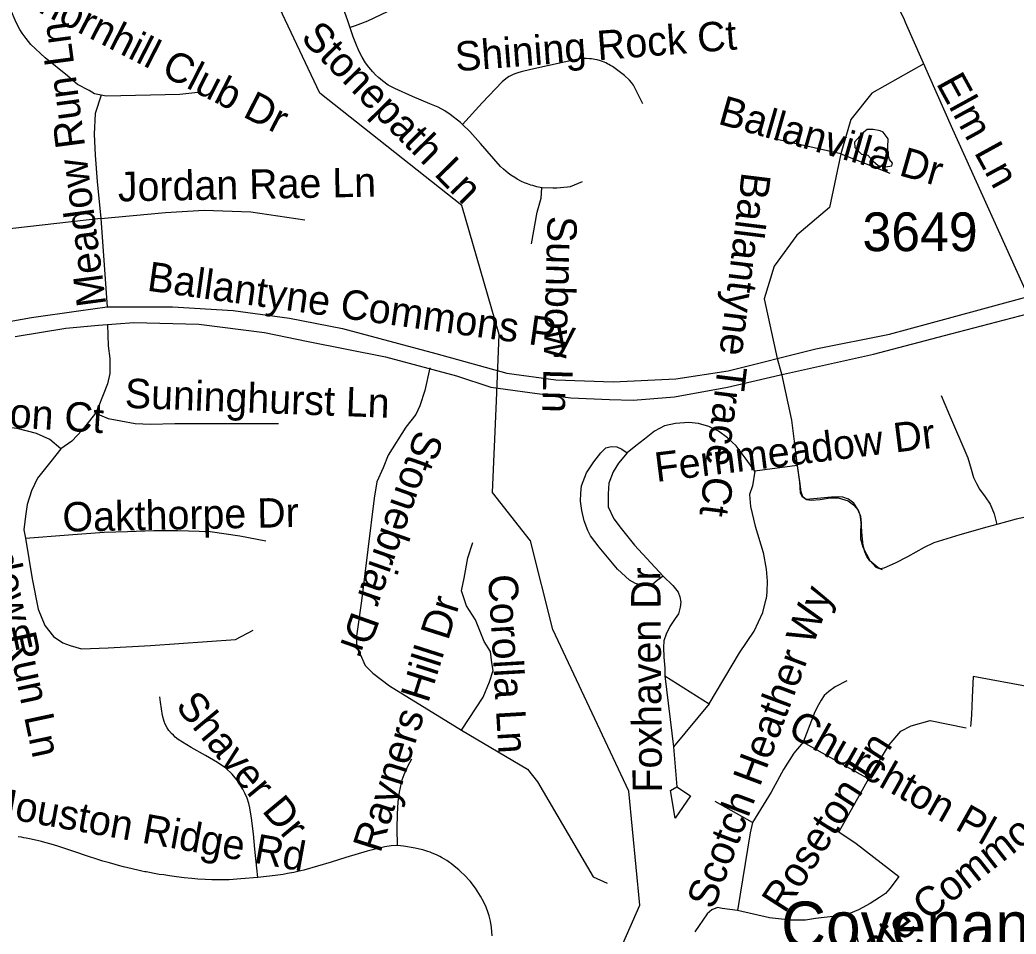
# Model space of a CAD drawing. Extents: x 1383679 to 1536984, y 460658 to 651027.
# Drawn here: x 1453218 to 1456433, y 478691 to 481642 of the extents above; entities that cross this region are included whole.
import ezdxf

# ---------------------------------------------------------------- set-up
doc = ezdxf.new("R2010")
doc.units = 0
for name, color, linetype in [('Exist Cultural Church Label', 7, 'Continuous'), ('Exist Hydrographic Creek Single Shore', 7, 'Continuous'), ('Exist Hydrographic Misc Water Feature', 7, 'Continuous'), ('Exist Road Non-System Type 51', 7, 'Continuous'), ('Exist Road Non-System Type 51 Label', 7, 'Continuous'), ('Exist Road Secondary Type 51 Attributed', 7, 'Continuous'), ('Exist Road Secondary Type 51 Label', 7, 'Continuous'), ('Exist Road Secondary Type 51 Number Label', 7, 'Continuous')]:
    doc.layers.add(name, color=color, linetype=linetype)

msp = doc.modelspace()

# ---------------------------------------------------------------- linework, layer by layer
at = {"layer": 'Exist Hydrographic Creek Single Shore'}
msp.add_lwpolyline([(1454515.4, 478187.7), (1454889, 478340.4), (1455120.5, 478561.6), (1455218.3, 478784.1), (1455183.2, 479152.5), (1454937.8, 479674), (1454865.3, 479959.8), (1454743.1, 480116.4), (1454756.2, 480411.6), (1454764.5, 480626.1), (1454643.5, 481042.1), (1454185.7, 481405.5), (1453861.2, 482093.8), (1453724.2, 482339.5), (1453677.2, 482498), (1453550.2, 482618.2), (1453423.9, 482707.8), (1453281.8, 482670.9), (1452824, 482655.1), (1452497.8, 482823.6), (1452051.2, 482927.9), (1451604.2, 483110.8), (1451358.9, 483344.6)], dxfattribs=at)
at = {"layer": 'Exist Hydrographic Misc Water Feature'}
msp.add_lwpolyline([(1455935.6, 481274.7), (1455911, 481247.3), (1455912.8, 481229.2), (1455934.4, 481208.2), (1455954.4, 481204.6), (1455972, 481186.1), (1455987.8, 481171.9), (1456011.7, 481167.3), (1456031.8, 481171), (1456033.8, 481179.2), (1456024.1, 481190.9), (1456018.5, 481209), (1456018.9, 481231.2), (1456019.4, 481257.4), (1456003.7, 481279.1), (1455993.8, 481283.4), (1455971.8, 481287.9), (1455951.8, 481288.3), (1455935.6, 481274.7)], dxfattribs=at)
at = {"layer": 'Exist Road Non-System Type 51'}
msp.add_line((1453479.1, 481000.2), (1453499, 480715.7), dxfattribs=at)
for points in [[(1454646.3, 481304.4), (1454640.2, 481310.4), (1454606.4, 481336), (1454589.6, 481347.6), (1454567.8, 481359.8), (1454540.8, 481371.1), (1454484.8, 481394.3), (1454427.6, 481420.5), (1454406.5, 481431.2), (1454388.4, 481444.4), (1454375.3, 481455.4), (1454365.5, 481464.8), (1454357.1, 481473.8), (1454343.6, 481488.8), (1454333.6, 481503), (1454322.5, 481521), (1454313.5, 481537.6), (1454309, 481547.2), (1454303.6, 481560.3), (1454293.5, 481586.7), (1454276, 481638.1), (1454241.4, 481735.6), (1454218.8, 481806.1), (1454213.2, 481831.4)], [(1454833.9, 481812.2), (1454739, 481781.7), (1454681, 481765.8), (1454639.6, 481755.8), (1454589.4, 481743.4), (1454572.4, 481739.2), (1454552.5, 481733.3), (1454532.3, 481726.8), (1454515.3, 481719.6), (1454477, 481702.4), (1454423.7, 481677.1), (1454382.4, 481657.4), (1454339.7, 481638), (1454317.4, 481628.9), (1454299.6, 481622.4), (1454283.6, 481617.2)], [(1453480.4, 481398.5), (1453458.7, 481403.1), (1453441.2, 481413.3), (1453403.8, 481432.6), (1453371.1, 481460.9), (1453298.8, 481518.8), (1453253.3, 481562.1), (1453237.9, 481581.2), (1453225.4, 481598.7), (1453217.8, 481610.5), (1453212.3, 481620.5), (1453202, 481640.9), (1453179.1, 481696.8), (1453179, 481698.7)], [(1455228.6, 481370.2), (1455200.4, 481426.3), (1455198.1, 481431.2), (1455191.9, 481439.8), (1455185, 481447.1), (1455169.2, 481461.8), (1455130.2, 481491.2), (1455124.3, 481494.6), (1455118.2, 481498.1), (1455114, 481500.2), (1455109, 481502.8), (1455103.8, 481505.3), (1455098.5, 481507.6), (1455091.2, 481509.9), (1455081.3, 481512.2), (1455073.5, 481513.7), (1455062.4, 481515.5), (1455055.9, 481516.4), (1455045.2, 481517.2), (1455042, 481517.2), (1455038.2, 481517), (1455031.7, 481516.6), (1455023.9, 481515.8), (1454989.1, 481508.6), (1454920.7, 481493.5), (1454866.4, 481481.3), (1454835.1, 481474.2), (1454824.9, 481471.1), (1454815.2, 481467.7), (1454807.2, 481464.3), (1454800.7, 481461.2), (1454797.1, 481459.3), (1454791.4, 481455.9), (1454774, 481441.7), (1454709.3, 481373.8), (1454646.3, 481304.4)], [(1456134.6, 481499.4), (1455967.5, 481404.8), (1455899, 481320.5), (1455867.4, 481209.8)], [(1453792.2, 481407.1), (1453733.6, 481401.3), (1453496.1, 481395.2), (1453480.4, 481398.5)], [(1453480.4, 481398.5), (1453461.1, 481339.7), (1453457.1, 481273.1), (1453461.1, 481205.4), (1453467.1, 481120.2), (1453479.1, 481000.2)], [(1454902.5, 481099.7), (1454891, 481101.5), (1454886.2, 481102.6), (1454873.2, 481106.6), (1454866.4, 481108.3), (1454855.5, 481112.3), (1454846.5, 481115.6), (1454836.4, 481120.2), (1454822.3, 481127.8), (1454815, 481132.4), (1454802.6, 481140.8), (1454793.8, 481147.1), (1454786.1, 481153.2), (1454778.2, 481160.3), (1454769.3, 481168.7), (1454704.8, 481242.2), (1454669.7, 481281.1), (1454646.3, 481304.4)], [(1455867.4, 481209.8), (1455651.5, 481257.3)], [(1455867.4, 481209.8), (1455830.6, 481035.9), (1455725.3, 480946.3), (1455651.5, 480846.2), (1455619.9, 480740.8), (1455661.7, 480548.6)], [(1455867.4, 481209.8), (1456025.4, 481146.6)], [(1455032.4, 481118.7), (1454993.7, 481103), (1454984.7, 481102), (1454950.9, 481099), (1454938, 481098.4), (1454903.5, 481099.6), (1454902.5, 481099.7)], [(1454868.9, 480919.3), (1454887.6, 481021.3), (1454899.7, 481066), (1454902.5, 481099.7)], [(1453479.1, 481000.2), (1453687.6, 481020.1), (1453812.6, 481028), (1453963.2, 481022.4), (1454137.3, 480996.3)], [(1453479.1, 481000.2), (1453195.4, 480968), (1453081.5, 480952.1), (1452990.4, 480927.2), (1452773.2, 480872.8)], [(1453499, 480715.7), (1453710.5, 480715.7), (1453906, 480704.1), (1454087.5, 480678.9), (1454259, 480646), (1454560.2, 480564.8), (1454789.6, 480500.9), (1454947.2, 480479.6), (1455132.7, 480473.8), (1455334.2, 480483.5), (1455503.7, 480508.6), (1455787, 480580.2), (1456024.3, 480627.2), (1456214.6, 480678.6), (1456472, 480748.3)], [(1453092.1, 480651.8), (1453255.7, 480680.9), (1453407.3, 480702.2), (1453499, 480715.7)], [(1453202.5, 480619.8), (1453365.5, 480646.1), (1453471.5, 480656.7), (1453585.6, 480664.6), (1453794.8, 480659.3), (1454006.8, 480632.9), (1454148.1, 480603.9), (1454398.1, 480553.8), (1454626.3, 480493.2), (1454737.7, 480456.3), (1454887.2, 480435.2), (1454995.9, 480422), (1455120.9, 480416.8), (1455196.9, 480414.1), (1455330.1, 480424.7), (1455501.3, 480456.3), (1455672.5, 480495.9), (1455972.2, 480562.9), (1456222.2, 480628.6), (1456494.2, 480699.2)], [(1453500.1, 480657.9), (1453502.8, 480589.8), (1453508.2, 480549), (1453508.2, 480516.3), (1453508.2, 480499.9), (1453500.1, 480467.2), (1453486.5, 480431.8), (1453470.1, 480390.9), (1453462, 480371.8)], [(1455661.7, 480548.6), (1455675.5, 480499.1)], [(1454540.8, 480518.9), (1454524.5, 480445.3), (1454508.2, 480396.3), (1454495.9, 480367.6), (1454463.2, 480326.7), (1454406, 480236.8), (1454389.7, 480195.9), (1454369.2, 480150.9), (1454361.1, 480097.8), (1454320.2, 479766.6), (1454303.9, 479652.1), (1454303.9, 479627.6), (1454316.1, 479594.9), (1454332.5, 479558.1), (1454357, 479533.5), (1454410.1, 479492.6), (1454643, 479349.5)], [(1455675.5, 480499.1), (1455707.6, 480349.3), (1455726.1, 480203.8)], [(1456190.6, 480429.7), (1456214.5, 480372.9), (1456277, 480227.8), (1456287.6, 480191.7), (1456295, 480164.6), (1456304.5, 480145.2), (1456314.8, 480126.8), (1456332.9, 480102.1), (1456349.2, 480078.7), (1456361.6, 480047), (1456371.1, 480013.1)], [(1453462, 480371.8), (1453418.4, 480317.4), (1453385.7, 480281.9), (1453350.3, 480257.4)], [(1453462, 480371.8), (1453502.8, 480355.5), (1453543.6, 480347.3), (1453589.9, 480339.2), (1453638.9, 480336.4), (1453717.9, 480339.2), (1454052.8, 480339.2)], [(1455589.9, 480185.3), (1455557.9, 480228.1), (1455529.4, 480267.3), (1455500.9, 480292.3), (1455472.3, 480313.7), (1455441, 480329.2), (1455408.2, 480338.6), (1455376.1, 480342.2), (1455333.4, 480338.6), (1455297.7, 480331.5), (1455265.6, 480313.7), (1455233.6, 480288.7), (1455205.1, 480267.3), (1455178.1, 480244.4)], [(1453350.3, 480257.4), (1453314.9, 480287.4), (1453271.4, 480306.5), (1453208.7, 480322.8), (1453159.7, 480328.3), (1453110.7, 480331), (1453059, 480325.5), (1453018.1, 480314.6), (1452974.6, 480298.3), (1452917.4, 480265.6)], [(1453350.3, 480257.4), (1453317.6, 480216.5), (1453274.1, 480162), (1453255, 480121.2), (1453241.4, 480077.6), (1453236, 480039.4), (1453230.5, 479995.8), (1453236, 479968.6)], [(1455294.2, 479846.5), (1455274, 479831.7), (1455260.3, 479820.5), (1455245.4, 479815.5), (1455222.9, 479816.7), (1455204.2, 479823), (1455185.6, 479833), (1455146.9, 479869.1), (1455087.1, 479940.2), (1455059.7, 479976.3), (1455051, 479993.8), (1455038.5, 480025), (1455031.1, 480058.6), (1455027.3, 480088.6), (1455028.6, 480113.5), (1455029.8, 480137.2), (1455046, 480179.6), (1455069.7, 480215.7), (1455092.1, 480244.4), (1455108.3, 480260.6), (1455125.7, 480264.4), (1455144.4, 480263.1), (1455160.6, 480255.6), (1455178.1, 480244.4)], [(1455178.1, 480244.4), (1455149.4, 480210.8), (1455132, 480183.3), (1455118.3, 480145.9), (1455115.8, 480112.2), (1455115.8, 480069.9), (1455134.5, 480031.2), (1455158.7, 479999.8), (1455201.5, 479946.3), (1455294.2, 479846.5)], [(1455589.9, 480185.3), (1455581.6, 480137.9), (1455572.1, 480109.4), (1455575.3, 480071.3), (1455591.1, 480007.9), (1455616.5, 479922.2), (1455626, 479868.3), (1455629.2, 479830.2), (1455628.3, 479795.9), (1455625.8, 479773.5)], [(1455726.1, 480203.8), (1455589.9, 480185.3)], [(1455726.1, 480203.8), (1455733.6, 480149), (1455736.1, 480116.6), (1455741, 480104.1), (1455756, 480094.1), (1455770.9, 480091.6), (1455800.8, 480094.1), (1455833.2, 480099.1), (1455858.1, 480099.1), (1455890.5, 480089.1), (1455907.9, 480076.7), (1455922.9, 480059.2), (1455930.4, 480039.3), (1455932.9, 480016.8), (1455930.4, 479994.4), (1455930.4, 479967), (1455937.8, 479939.5), (1455950.3, 479917.1), (1455960.3, 479897.2), (1455980.2, 479874.7), (1456000.1, 479867.3)], [(1456371.1, 480013.1), (1456338.6, 480004.2), (1456251.5, 479979.7), (1456167.6, 479954.2), (1456135.6, 479938.5), (1456082.1, 479908.9), (1456042.6, 479888.4), (1456005.9, 479872.1), (1455995.6, 479869.7), (1455986.6, 479873.7), (1455961.1, 479895.2), (1455950.6, 479909.8), (1455944.9, 479924.5), (1455939.1, 479944.7), (1455935.9, 479976.3), (1455932.5, 480019.9), (1455929.2, 480043.8), (1455921, 480063.5), (1455909.5, 480081.5), (1455892.2, 480094.7), (1455873.4, 480101.2), (1455860.2, 480102.1), (1455837.1, 480101.2), (1455791.1, 480096.3), (1455755.8, 480093.8), (1455744.2, 480102.1), (1455739.4, 480118.5), (1455735.4, 480143.9), (1455728.1, 480195.2), (1455726.5, 480207.1)], [(1456541.2, 480053.1), (1456522.8, 480047), (1456462.8, 480036.3), (1456433.1, 480029.8), (1456371.1, 480013.1)], [(1453236, 479968.6), (1453374.8, 479979.5), (1453489.2, 479987.7), (1453565.4, 479990.4), (1453649.8, 479993.1), (1453726.1, 479993.1), (1453832.3, 479990.4), (1453927.6, 479976.8), (1454012, 479960.4)], [(1453236, 479968.6), (1453257.7, 479837.8), (1453276.8, 479739.7), (1453297.7, 479686.4), (1453326, 479651.4), (1453356.4, 479631.1), (1453380.3, 479622.5), (1453416.2, 479611.9), (1453502.8, 479614.4), (1453638.9, 479622.5), (1453913.9, 479641.6), (1453971.1, 479671.6)], [(1454643, 479349.5), (1454712.5, 479455.8), (1454732.9, 479504.9), (1454745.1, 479541.7), (1454741.1, 479566.2), (1454737, 479603), (1454716.5, 479635.7), (1454687.9, 479705.2), (1454659.3, 479750.2), (1454643, 479799.3), (1454651.2, 479840.2), (1454663.4, 479905.6), (1454679.8, 479954.7)], [(1455294.2, 479846.5), (1455325.1, 479815.5), (1455342.5, 479794.3), (1455347.5, 479779.3), (1455351.3, 479761.9), (1455348.8, 479745.7), (1455343.8, 479724.5), (1455332.6, 479709.5), (1455315.1, 479684), (1455303.9, 479659), (1455296.4, 479637.8), (1455295.2, 479615.4), (1455296.4, 479584.2), (1455298.9, 479549.3), (1455298.9, 479524.4)], [(1455442.1, 479433.6), (1455540.4, 479598.6), (1455587.9, 479668.4), (1455615.2, 479729.2), (1455625.8, 479773.5)], [(1455298.9, 479524.4), (1455442.1, 479433.6)], [(1455298.9, 479524.4), (1455327.5, 479295.1)], [(1455886.1, 479508.7), (1455848.4, 479488.5), (1455828.3, 479473.4), (1455813.2, 479460.9), (1455803.2, 479445.8), (1455795.6, 479430.7), (1455783, 479408), (1455745.3, 479309.9)], [(1456480.5, 479488.2), (1456294.6, 479522.8), (1456290.9, 479454.7), (1456288.8, 479398.5), (1456286.5, 479371.5), (1456285.8, 479361.4)], [(1453985.8, 478873.9), (1453982.8, 478903.3), (1453975.8, 478965.5), (1453971.9, 479014.1), (1453965.5, 479065), (1453959.9, 479098), (1453956.2, 479112.9), (1453950.9, 479129.4), (1453944, 479145.2), (1453937, 479158.7), (1453927.9, 479173.5), (1453917.9, 479189), (1453903.1, 479207), (1453882, 479226.8), (1453855.9, 479245), (1453816.3, 479267.8), (1453770, 479293.4), (1453729, 479318.5), (1453718.9, 479327), (1453713, 479332.4), (1453706.6, 479338.7), (1453698.7, 479348.3), (1453692.8, 479356.9), (1453687, 479368.5), (1453683.7, 479376.6), (1453678.4, 479396.9), (1453671, 479439.1), (1453669.3, 479457)], [(1455442.1, 479433.6), (1455327.5, 479295.1)], [(1455956.5, 479191.7), (1456022.9, 479302), (1456060.4, 479346.2), (1456094.4, 479363.3), (1456155.6, 479380.3), (1456271.2, 479356.5)], [(1454643, 479349.5), (1454855.5, 479222.8), (1454888.1, 479181.9), (1455067.9, 478875.2), (1455112.9, 478854.8)], [(1455327.5, 479295.1), (1455337.5, 479166.7)], [(1455745.3, 479309.9), (1455715.2, 479274.7), (1455682.5, 479221.9), (1455642.3, 479148.9), (1455581.9, 479050.8)], [(1455745.3, 479309.9), (1455956.5, 479191.7)], [(1454436.7, 478976.4), (1454435.3, 479031.3), (1454436.1, 479078.1), (1454438.2, 479117.8), (1454442.8, 479148.9), (1454449.7, 479179.5), (1454451.9, 479188.9), (1454457.7, 479206.2), (1454462.2, 479216.1), (1454470.1, 479232.7), (1454483, 479256.1)], [(1455956.5, 479191.7), (1455861, 479020.6)], [(1455337.5, 479166.7), (1455382.3, 479136.8), (1455332.5, 479064.5), (1455317.5, 479154.3), (1455337.5, 479166.7)], [(1455581.9, 479050.8), (1455461.2, 479118.7)], [(1455861, 479020.6), (1455785.6, 479060.8)], [(1455581.9, 479050.8), (1455574.4, 479018.1), (1455534.1, 478766.5)], [(1453985.8, 478873.9), (1453931.3, 478868.9), (1453893.1, 478866.4), (1453859.3, 478865.9), (1453836.8, 478866.3), (1453815.6, 478867.4), (1453791.7, 478868.6), (1453773, 478870.3), (1453748.3, 478872.6), (1453722.7, 478875.8), (1453700.2, 478878.7), (1453682.2, 478881.6), (1453666.9, 478883.7), (1453651.2, 478886.5), (1453635.9, 478889.2), (1453624.9, 478891.5), (1453621.2, 478892.1), (1453611.1, 478894.2), (1453602.5, 478896.1), (1453580.1, 478901.6), (1453552.4, 478908.1), (1453536.2, 478912.3), (1453525.5, 478915), (1453506.6, 478920.4), (1453485.4, 478926.6), (1453468.9, 478931.4), (1453436.3, 478941.9), (1453394.8, 478956.1), (1453362.3, 478967.3), (1453340.5, 478974.7), (1453318.3, 478981), (1453298.1, 478986.3), (1453287.2, 478989.4), (1453263.7, 478995.3), (1453248.9, 478998.4), (1453237.7, 479001), (1453230.6, 479002), (1453222.8, 479003.2), (1453211.7, 479004.3)], [(1455861, 479020.6), (1455916.3, 478982.8), (1456054.6, 478877.2)], [(1454436.7, 478976.4), (1454416.3, 478975.3), (1454395.3, 478972.2), (1454338.4, 478958.8), (1454270, 478938.3), (1454222.2, 478923.1), (1454178.2, 478909.9), (1454134.4, 478897.5), (1454115.1, 478893), (1454101.3, 478889.6), (1454081.4, 478886), (1454067.1, 478883.6), (1454041.4, 478879.9), (1453985.8, 478873.9)], [(1454741.9, 478685.2), (1454739.4, 478711.8), (1454736.4, 478733), (1454731.8, 478749.5), (1454728.9, 478759.8), (1454722.4, 478777.8), (1454714.2, 478796.1), (1454704.8, 478813.5), (1454687.8, 478839), (1454670.9, 478861.8), (1454651.5, 478882.5), (1454642.3, 478890.9), (1454633.9, 478898.8), (1454619.6, 478910.4), (1454610.2, 478917.3), (1454603.9, 478921.9), (1454595.1, 478928), (1454588.4, 478932.4), (1454578.9, 478937.8), (1454573, 478940.8), (1454562.1, 478946.2), (1454548.3, 478952.1), (1454541.4, 478954.8), (1454533.8, 478957.5), (1454527.7, 478959.4), (1454518.3, 478962.4), (1454507.4, 478964.9), (1454493.4, 478968), (1454455.8, 478974.6), (1454436.7, 478976.4)], [(1456054.6, 478877.2), (1456026.9, 478839.4), (1456011.8, 478821.8), (1455991.7, 478809.2), (1455961.5, 478789.1), (1455923.8, 478769), (1455898.7, 478758.9)], [(1455534.1, 478766.5), (1455483.9, 478774), (1455468.8, 478776.5), (1455451.2, 478769), (1455436.1, 478756.4), (1455395.9, 478698.5)], [(1455898.7, 478758.9), (1455850.9, 478748.9), (1455785.6, 478741.3), (1455752.9, 478736.3), (1455705.1, 478736.3), (1455637.2, 478743.8), (1455534.1, 478766.5)], [(1455898.7, 478758.9), (1455928.9, 478643.2)]]:
    msp.add_lwpolyline(points, dxfattribs=at)
at = {"layer": 'Exist Road Secondary Type 51 Attributed'}
msp.add_lwpolyline([(1455135.8, 483072), (1455511.9, 482538.5), (1455640.3, 482366.3), (1455766.5, 482173.6), (1455847, 482046.7), (1455900.8, 481978.7), (1455952.1, 481875.7), (1455974.3, 481838.4), (1455998.2, 481794.3), (1456021.5, 481746.2), (1456046.2, 481696), (1456071.2, 481642.8), (1456075, 481634.1), (1456227.8, 481288.6), (1456472, 480748.3)], dxfattribs=at)

# ---------------------------------------------------------------- texts
at = {"layer": 'Exist Cultural Church Label'}
msp.add_text('Covenant Baptist', height=150, rotation=0, dxfattribs=at).set_placement((1455674.5, 478645.8))
at = {"layer": 'Exist Road Non-System Type 51 Label'}
for s, rotation, p in [('Thornhill Club Dr', 332.9058, (1453204.5, 481703.9)), ('Meadow Run Ln', 97.601, (1453496.9, 480722.5)), ('Stonepath Ln', 314.4903, (1454120.6, 481580.5)), ('Shining Rock Ct', 4.4666, (1454625.9, 481475.4)), ('Ballanvilla Dr', 344.1267, (1455467.2, 481307)), ('Jordan Rae Ln', 1.0805, (1453534.7, 481055.6)), ('Ballantyne Trace Ct', 262.9729, (1455547.5, 481152.5)), ('Sunbow Ln', 268.4171, (1454921, 481009.8)), ('Ballantyne Commons Py', 352.0053, (1453625.4, 480768)), ('Suninghurst Ln', 357.8288, (1453555.2, 480389.6)), ('Hatton Ct', 356.3558, (1452950, 480341.8)), ('Fernmeadow Dr', 7.0307, (1455272.1, 480150)), ('Stonebriar Dr', 250.524, (1454497.6, 480322.5)), ('Meadow Run Ln', 282.0788, (1453066.8, 480159.5)), ('Oakthorpe Dr', 1.1527, (1453356.1, 479989.6)), ('Foxhaven Dr', 90.4484, (1455290.2, 479147.9)), ('Corolla Ln', 273.3715, (1454728.6, 479849.7)), ('Scotch Heather Wy', 69.3785, (1455456.2, 478767)), ('Rayners Hill Dr', 72.3522, (1454381, 478949.7)), ('Skipton Ln', 12.0643, (1452679.5, 479495.1)), ('Shaver Dr', 309.6666, (1453717, 479425.2)), ('Churchton Pl', 330.6202, (1455690.4, 479336)), ('Roseton Ln', 57.3465, (1455686.1, 478754.6)), ('Southgate Commons Dr', 38.1699, (1455663.6, 478351.2)), ('Houston Ridge Rd', 349.8608, (1453107.8, 479075.8))]:
    msp.add_text(s, height=95, rotation=rotation, dxfattribs=at).set_placement(p)
at = {"layer": 'Exist Road Secondary Type 51 Label'}
msp.add_text('Elm Ln', height=95, rotation=298.7678, dxfattribs=at).set_placement((1456173.3, 481436.9))
at = {"layer": 'Exist Road Secondary Type 51 Number Label'}
msp.add_text('3649', height=125, dxfattribs=at).set_placement((1455936.9, 480895.2))

doc.saveas('drawing.dxf')
